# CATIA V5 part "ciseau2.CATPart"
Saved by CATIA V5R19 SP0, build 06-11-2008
Part number: ciseau2
Publications: "D-vis/goupille1"
Bounding box of the stored display mesh (mm): x -136.372 to 15.617, y -131.102 to 16.048, z 0 to 10
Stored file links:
  C:\Documents and Settings\alenoir\Bureau\mécanisme\ciseau2.CATPart
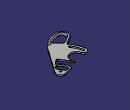
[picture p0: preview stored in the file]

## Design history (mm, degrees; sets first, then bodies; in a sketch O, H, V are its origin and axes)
Parameters
  `D-vis/goupille1` = 25 mm
  LENGTH = 0 mm
Body1 (main body)
  Sketch1 on xy-plane, origin (0.6173, 1.0615, 0), H (0.5482, -0.8363, 0), V (0.8363, 0.5482, 0)
    line L1 (13.9342, 5.5533) -> (55.2099, -98.0146)
    point P1 (16.1474, 0)
    point P2 (0, 200)
    circle A1 centre (0, 0) radius 4
    arc A2 centre (0, 0) radius 125 from (-42.7525, -117.4616) to (9, -124.6756) ccw
    arc A3 centre (42.6692, -103.0126) radius 13.5 from (49.3316, -114.754) to (55.2099, -98.0146) ccw
    point P4 (49.3316, -114.754)
    point P8 (0, -22.5)
    arc A4 centre (-27.3616, -75.1754) radius 22.3607 from (-35.0094, -96.1876) to (-27.3616, -52.8147) ccw
    point P9 (-27.3616, -75.1754)
    arc A5 centre (0, 0) radius 15 from (13.9342, 5.5533) to (-14.2541, 4.6713) ccw
    line L2 (20.261, -28.5393) -> (22.6387, -47.3652)
    point P10 (22.6387, -47.3652)
    point P11 (22.1252, -52.8147)
    line L3 (-27.3616, -52.8147) -> (22.1252, -52.8147)
    line L4 (22.1252, -52.8147) -> (22.4079, -49.8147)
    line L5 (22.4079, -49.8147) -> (17.3857, -49.8147)
    point P14 (17.3857, -49.8147)
    line L6 (17.3857, -49.8147) -> (22.6387, -47.3652)
    point P15 (22.6387, -47.3652)
    point P16 (-35.0094, -96.1876)
    spline S1 through (49.3316, -114.754) (59.6421, -124.3692) (58.5484, -140.7762) (54.1733, -153.5372) (48.7044, -165.9336) (39.5897, -177.6008) (22.8186, -177.9654) (9, -165.7037)
    line L7 (9, -165.7037) -> (9, -124.6756)
    point P17 (9, -165.7037)
    construction line L8 (0, 0) -> (-27.3616, -75.1754)
    arc A6 centre (-38.881, -106.8246) radius 11.3197 from (-42.7525, -117.4616) to (-35.0094, -96.1876) cw
    point P20 (-49.6377, -103.2994)
    construction line L9 (-49.6377, -103.2994) -> (-14.2541, 4.6713)
    construction line L10 (0, 0) -> (-38.881, -106.8246)
    construction line L11 (0, 0) -> (42.6692, -103.0126)
    axis line L12 (0, 0) -> (0, -125)
    point P22 (0, -125)
    arc A7 centre (0, 0) radius 35 from (-24.102, -25.379) to (20.261, -28.5393) ccw
    line L13 (-14.2541, 4.6713) -> (-24.102, -25.379)
    point P24 (-24.102, -25.379)
    point P25 (-24.102, -25.379)
    point P26 (49.3316, -114.754)
    point P27 (9, -165.7037)
    radius A1 = 4
    radius A2 = 125
    radius A3 = 13.5
    radius A4 = 22.3607
    distance P9 O = 80
    distance P14 L4 = 5
    angle L6 L5 = 25
    distance P11 L1 = 14
    distance L5 L3 = 3
    radius A5 = 15
    angle L12 L11 = 22.5
    angle L10 L12 = 20
    distance L7 L12 = 9
    radius A7 = 35
    length L7 = 41.0281
    coincidence: P1 L1, P1 H, P15 L4, P26 P4, P27 P17, A6 P20, P22 A2, P10 P15, P24 A7, L9 P25, P16 L10
    tangency: A3 L1, A3 A2, A5 L1, A4 L3, A6 A2, A6 A4, L9 A5, L9 A6, L13 A5
    horizontal: L3 H
    vertical: L7 V, L12 V
  Pad1: profile Sketch1, direction (0, 0, 1), length 10
  Sketch2 on start face of Pad1, origin (0.6173, 1.0615, 0), H (0.5482, -0.8363, 0), V (0.8363, 0.5482, 0)
    spline S1 through (14.4994, -165.2858) (23.5036, -173.1647) (37.7673, -172.7797) (45.1958, -161.5242) (49.6979, -150.2687) (53.5247, -137.6625) (54.6502, -125.2814) (44.9707, -121.4545)
    spline S2 through (14.4994, -135.8616) (17.0577, -129.1082) (27.4125, -125.0563)
    line L1 (14.4994, -165.2858) -> (14.4994, -135.8616)
    point P1 (14.4994, -165.2858)
    point P2 (14.4994, -135.8616)
    line L2 (27.4125, -125.0563) -> (44.9707, -121.4545)
    point P3 (27.4125, -125.0563)
    point P4 (44.9707, -121.4545)
    point P5 (14.4994, -165.2858)
    point P6 (14.4994, -135.8616)
    point P7 (27.4125, -125.0563)
    point P8 (44.9707, -121.4545)
    coincidence: P5 P1, P6 P2, P7 P3, P8 P4
    vertical: L1 V
  Pocket1: profile Sketch2, direction (0, 0, 1), through (limit type 6)
  Sketch3 on start face of Pad1, origin (0.6173, 1.0615, 0), H (0.5482, -0.8363, 0), V (0.8363, 0.5482, 0)
    circle A1 centre (0, 0) radius 125.4928
  Pocket2: profile Sketch3, direction (0, 0, 1), length 5
  Sketch4 on end face of Pocket2, origin (0.6173, 1.0615, 5), H (0.5482, -0.8363, 0), V (0.8363, 0.5482, 0)
    construction arc A1 centre (0, 0) radius 115 from (-39.3323, -108.0647) to (0, -115) ccw
    point P2 (0, -115)
    arc A2 centre (-39.3323, -108.0647) radius 3 from (-40.3584, -110.8837) to (-38.3063, -105.2456) cw
    arc A3 centre (0, -115) radius 3 from (0, -112) to (0, -118) cw
    arc A4 centre (0, 0) radius 112 from (-38.3063, -105.2456) to (0, -112) ccw
    arc A5 centre (0, 0) radius 118 from (0, -118) to (-40.3584, -110.8837) cw
    construction line L1 (0, 0) -> (0, -171.8681)
    axis line L2 (0, 0) -> (-39.3323, -108.0647)
    radius A3 = 3
    angle L2 L1 = 20
    radius A1 = 115
    tangency: A4 A3, A3 A5, A5 A2, A2 A4
    concentricity: A4 O, A5 O
    vertical: L1 V
    coincidence: P2 L1
  Pocket3: profile Sketch4, direction (0, 0, -1), through (limit type 6)
  Sketch5 on end face of Pad1, origin (0.6173, 1.0615, 10), H (0.5482, -0.8363, 0), V (0.8363, 0.5482, 0)
    arc A1 centre (0, 0) radius 30 from (-16.6529, -24.9536) to (16.4319, -25.0997) ccw
    spline S1 through (9.5618, -8) (15.8251, -11.1664) (18.1685, -18.1971) (16.4319, -25.0997)
    spline S2 through (-9.4212, -8) (-13.7882, -9.8881) (-16.5578, -14.1491) (-17.623, -19.6885) (-16.6529, -24.9536)
    point P1 (16.4319, -25.0997)
    point P2 (-16.6529, -24.9536)
    line L1 (-9.4212, -8) -> (9.5618, -8)
    point P3 (-9.4212, -8)
    point P4 (9.5618, -8)
    reference projected circle E1 centre (0, 0) radius 4 from Sketch1.A1
    point P5 (9.5618, -8)
    point P6 (16.4319, -25.0997)
    point P7 (-9.4212, -8)
    point P8 (-16.6529, -24.9536)
    radius A1 = 30
    distance E1 L1 = 4
    coincidence: P6 A1, P8 A1, P6 P1, P8 P2, P7 P3, P5 P4
    horizontal: L1 H
  Pocket4: profile Sketch5, direction (0, 0, -1), through (limit type 6)
  Sketch6 on end face of Pad1, origin (0, 0, 10), H (1, 0, 0), V (0, 1, 0)
    circle A1 centre (0.6173, 1.0615) radius 30
    reference projected arc E1 centre (0.6173, 1.0615) radius 30 from (-29.3817, 1.3084) to (-11.3657, -26.4414) ccw from edge [end face of Pad1 | face of Pocket4 from Sketch5.A1]
    reference projected arc E2 centre (0.6173, 1.0615) radius 30 from (-29.3817, 1.3084) to (-11.3657, -26.4414) ccw from edge [end face of Pad1 | face of Pocket4 from Sketch5.A1]
    concentricity: A1 E1
    coincidence: A1 E2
